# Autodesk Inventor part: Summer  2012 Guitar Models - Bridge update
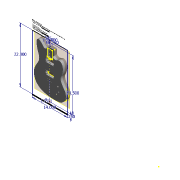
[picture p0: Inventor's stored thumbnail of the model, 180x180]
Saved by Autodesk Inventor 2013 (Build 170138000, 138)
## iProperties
Created: 2011-12
Part Number: Summer  2012 Guitar Models - Bridge update
Material: Generic
Document SubType Name: Modeling
Designer: Jeremy
Density: 1 g/cm^3
Author: Jeremy
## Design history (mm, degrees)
sketch "(ALL) Pocket Layout"
  geometry: L1 (-55.693, -76.531)-(-54.491, 0); L2 (-27.245, 0)-(-27.245, -267.97); L3 (-27.245, -267.97)-(-27.245, -279.73); L4 (-27.245, -279.73)-(-16.958, -279.73); L5 (-22.102, -267.97)-(-32.389, -267.97); L6 (-37.532, -279.73)-(-27.245, -279.73); L7 (-1.972, -79.756)-(-20.387, -79.756); L8 (-32.389, -267.97)-(-42.676, -267.97); L9 (-37.532, -279.73)-(-47.819, -279.73); L10 (-42.676, -267.97)-(-52.963, -267.97); L11 (-11.815, -267.97)-(-22.102, -267.97); L12 (8.442, -239.522)-(-62.932, -239.522); L13 (13.522, -237.236)-(-68.012, -237.236); L14 (-27.245, -239.522)-(-27.245, -237.236); L15 (-1.528, -267.97)-(-11.815, -267.97); L16 (8.442, -226.822)-(8.442, -239.522); L17 (-62.932, -239.522)-(-62.932, -226.822); L18 (-70.425, -226.822)-(-62.932, -226.822); L19 (-27.245, -129.921)-(-27.245, -127.635); L20 (-68.012, -90.297)-(13.522, -90.297); L21 (-68.012, -108.966)-(13.522, -108.966); L22 (8.442, -129.921)-(-62.932, -129.921); L23 (13.522, -127.635)-(-68.012, -127.635); L24 (-62.932, -100.711)-(-62.932, -88.011); L25 (-62.932, -129.921)-(-62.932, -117.221); L26 (-68.012, -127.635)-(-68.012, -90.297); L27 (-34.103, -79.756)-(-52.518, -79.756); L28 (8.442, -88.011)-(8.442, -100.711); L29 (8.442, -117.221)-(8.442, -129.921); L30 (13.522, -90.297)-(13.522, -127.635); L31 (-70.425, -100.711)-(-70.425, -117.221); L32 (-70.425, -117.221)-(-62.932, -117.221); L33 (-70.425, -108.966)-(-68.012, -108.966); L34 (-62.932, -100.711)-(-70.425, -100.711); L35 (-16.958, -279.73)-(-6.671, -279.73); L36 (-70.425, -210.312)-(-70.425, -226.822); L37 (-70.425, -218.567)-(-68.012, -218.567); L38 (-62.932, -210.312)-(-70.425, -210.312); L39 (-68.012, -237.236)-(-68.012, -199.898); L40 (-62.932, -210.312)-(-62.932, -197.612); L41 (15.935, -226.822)-(8.442, -226.822); L42 (15.935, -218.567)-(13.522, -218.567); L43 (-68.012, -218.567)-(13.522, -218.567); L44 (-68.012, -199.898)-(13.522, -199.898); L45 (-62.932, -197.612)-(8.442, -197.612); L46 (8.442, -210.312)-(15.935, -210.312); L47 (15.935, -210.312)-(15.935, -226.822); L48 (8.442, -197.612)-(8.442, -210.312); L49 (13.522, -199.898)-(13.522, -237.236); L50 (-54.491, 0)-(0, 0); L51 (-46.295, -13.03)-(-27.245, -13.03); L52 (-8.195, -13.03)-(-8.195, -63.83); L53 (-8.195, -63.83)-(-46.295, -63.83); L54 (-46.295, -63.83)-(-46.295, -13.03); L55 (-27.245, -13.03)-(-8.195, -13.03); L56 (0, 0)-(1.202, -76.531); L57 (15.935, -100.711)-(15.935, -117.221); L58 (15.935, -117.221)-(8.442, -117.221); L59 (15.935, -108.966)-(13.522, -108.966); L60 (8.442, -100.711)-(15.935, -100.711); L61 (-33.595, -80.264)-(-33.595, -87.503); L62 (-20.895, -80.264)-(-20.895, -87.503); L63 (-62.932, -88.011)-(-27.245, -88.011); L64 (-27.245, -88.011)-(8.442, -88.011); C1 r 1.587 at (-46.295, -13.03); C2 r 1.587 at (-46.295, -63.83); C3 r 1.587 at (-22.102, -267.97); C4 r 1.587 at (-27.245, -279.73); C5 r 1.587 at (-52.963, -267.97); C6 r 1.587 at (-42.676, -267.97); C7 r 1.587 at (-37.532, -279.73); C8 r 1.587 at (-32.389, -267.97); C9 r 1.587 at (-16.958, -279.73); C10 r 1.587 at (-11.815, -267.97); C11 r 1.587 at (-6.671, -279.73); C12 r 1.587 at (-1.528, -267.97); C13 r 1.587 at (-47.819, -279.73); C14 r 1.587 at (-8.195, -63.83); C15 r 1.587 at (-8.195, -13.03); C16 r 3.175 at (-52.963, -267.97); C17 r 3.175 at (-42.676, -267.97); C18 r 3.175 at (-32.389, -267.97); C19 r 3.175 at (-22.102, -267.97); C20 r 3.175 at (-11.815, -267.97); C21 r 3.175 at (-1.528, -267.97); C22 r 0.992 at (-68.012, -90.297); C23 r 0.992 at (13.522, -90.297); C24 r 0.992 at (13.522, -127.635); C25 r 0.992 at (-68.012, -127.635); C26 r 0.992 at (-68.012, -199.898); C27 r 0.992 at (13.522, -199.898); C28 r 0.992 at (13.522, -237.236); C29 r 0.992 at (-68.012, -237.236); A1 r 3.175 centre (-1.972, -76.581) between (-1.972, -79.756) and (1.202, -76.531); A2 r 3.175 centre (-52.518, -76.581) between (-55.693, -76.531) and (-52.518, -79.756); A3 r 0.508 centre (-34.103, -87.503) between (-34.103, -88.011) and (-33.595, -87.503); A4 r 0.508 centre (-20.387, -87.503) between (-20.895, -87.503) and (-20.387, -88.011); A5 r 0.508 centre (-20.387, -80.264) between (-20.387, -79.756) and (-20.895, -80.264); A6 r 0.508 centre (-34.103, -80.264) between (-33.595, -80.264) and (-34.103, -79.756); 25 further points
  constraints: 128 end point, 43 coincident, 35 centre point, 34 perpendicular, 29 equal radius, 27 parallel, 19 collinear, 17 equal length, 14 midpoint, 14 tangent, 12 point on circle, 9 point on line, 7 horizontal, 1 vertical, 1 other
  dimensions: "d0" = 3.175 diameter of C15; "d1" = 50.8 distance of L53.end L51.start; "d2" = 38.1 distance of L52.end L53.end; "d3" = 10.287 distance of L8.end L10.end; "d4" = 3.175 diameter of C9; "d5" = 71.374 distance of L22.start L22.end; "d7" = 16.51 distance of L31.start L31.end; "d8" = 7.493 distance of L31.end L25.end; "d9" = 37.338 distance of L20.end L23.start; "d10" = 81.534 distance of L23.start L23.end; "d11" = 188.214 distance between parallel lines of L15 L7; "d12" = 15.9258 distance between parallel lines of L53 L7; "d13" = 79.756 distance between parallel lines of L50 L27; "d14" = 35.687 distance between parallel lines of L2 L24 (= 0.5 x d5); "d18" = 28.448 distance between parallel lines of L8 L12; "d19" = 89.1 deg angle of L1 L27; "d20" = 89.1 deg angle of L7 L56 (= d19); "d21" = 56.896 dimension on A1 A2; "d22" = 3.175 radius of A2; "d24" = 11.7602 distance between parallel lines of L6 L8; "d25" = 10.287 distance of L6.start L3.end; "d190" = 8.255 distance between parallel lines of L63 L27; "d191" = 12.7 distance between parallel lines of L34 L63; "d192" = 12.7 distance between parallel lines of L62 L61; "d193" = 0.508 radius of A3; "d198" = 6.35 diameter of C16; "d224" = 1.98438 diameter of C22; "d229" = 54.49072 distance of L1.end L50.end (derived)
sketch "DC Profile"
  geometry: L1 (0.598, -38.095)-(0, 0); L2 (0.598, -38.095)-(6.428, -57.036); L3 (0, 0)-(-55.88, 0); L4 (-27.94, 0)-(-27.94, -264.048); L5 (8.442, -239.522)-(-62.932, -239.522) reference; L6 (8.442, -226.822)-(8.442, -239.522) reference; L7 (15.935, -226.822)-(8.442, -226.822) reference; L8 (15.935, -210.312)-(15.935, -226.822) reference; L9 (-27.94, -264.048)-(87.038, -330.431); L10 (87.038, -330.431)-(77.061, -347.71); C1 r 22.225 at (65.63, -275.47); C2 r 22.225 at (60.208, -319.588); C3 r 1.587 at (-1.528, -267.97) reference; C4 r 1.587 at (-6.671, -279.73) reference; C5 r 3.175 at (-1.528, -267.97) reference; C6 r 6.223 at (65.63, -275.47); C7 r 4.763 at (60.208, -319.588); C8 r 4.763 at (28.736, -339.371); A1 r 15.24 centre (76.454, -45.83) between (89.084, -54.359) and (66.661, -34.153); A2 r 577.126 centre (437.513, -476.355) between (66.661, -34.153) and (33.758, -63.977); A3 r 16.51 centre (22.207, -52.18) between (6.428, -57.036) and (33.758, -63.977); A4 r 116.188 centre (185.37, -119.388) between (89.084, -54.359) and (69.629, -129.58); A5 r 86.071 centre (155.369, -122.03) between (69.629, -129.58) and (82.565, -167.941); A6 r 609.6 centre (-433.07, -493.108) between (115.04, -226.297) and (82.565, -167.941); A7 r 121.92 centre (5.418, -279.659) between (115.845, -331.335) and (115.04, -226.297); A8 r 158.75 centre (-27.94, -264.048) between (-171.725, -331.335) and (115.845, -331.335); A9 r 121.92 centre (-61.298, -279.659) between (-170.92, -226.297) and (-171.725, -331.335); A10 r 12.7 centre (-55.88, -12.7) between (-55.88, 0) and (-67.52, -7.62); A11 r 609.6 centre (377.19, -493.108) between (-138.014, -167.259) and (-170.92, -226.297); A12 r 86.662 centre (-211.256, -120.935) between (-138.014, -167.259) and (-124.602, -119.803); A13 r 170.431 centre (-295.018, -122.03) between (-124.602, -119.803) and (-136.115, -60.412); A14 r 244.348 centre (124.259, 83.536) between (-117.009, 44.864) and (-102.671, -7.063); A15 r 279.4 centre (124.385, 40.602) between (-155.012, 41.929) and (-136.115, -60.412); A16 r 19.122 centre (-135.89, 41.838) between (-117.009, 44.864) and (-155.012, 41.929); A17 r 19.05 centre (-84.979, 0) between (-102.671, -7.063) and (-67.52, -7.62); A18 r 31.75 centre (28.736, -339.371) between (0.683, -324.504) and (47.295, -365.133); A19 r 38.1 centre (28.736, -339.371) between (-4.928, -321.53) and (51.006, -370.285); A20 r 1049.401 centre (927.915, -815.912) between (38.727, -258.609) and (0.683, -324.504); A21 r 1055.751 centre (927.915, -815.912) between (33.347, -255.236) and (-4.928, -321.53); A22 r 121.641 centre (-23.806, -266.435) between (47.295, -365.133) and (97.219, -278.661); A23 r 127.991 centre (-23.806, -266.435) between (51.006, -370.285) and (103.537, -279.299); A24 r 31.75 centre (65.63, -275.47) between (97.219, -278.661) and (38.727, -258.609); A25 r 38.1 centre (65.63, -275.47) between (103.537, -279.299) and (33.347, -255.236); 11 further points
  constraints: 51 point on circle, 30 centre point, 25 tangent, 12 end point, 7 coincident, 3 equal radius, 1 horizontal, 1 midpoint, 1 perpendicular, 1 point on line, 1 vertical, 10 other
  dimensions: "d78" = 121.92 radius of A9; "d79" = 121.92 radius of A7 (derived); "d80" = 609.6 radius of A6 (derived); "d81" = 116.18821 radius of A4; "d82" = 15.24 radius of A1; "d83" = 577.12575 radius of A2; "d84" = 609.6 radius of A11; "d85" = 86.66192 radius of A12; "d86" = 170.43088 radius of A13; "d87" = 279.4 radius of A15; "d88" = 19.12205 radius of A16; "d89" = 244.348 radius of A14; "d90" = 158.75 radius of A8; "d91" = 55.88 distance of L1.end L3.end; "d92" = 12.7 radius of A10; "d93" = 19.05 radius of A17; "d94" = 60.96 dimension on A16 L3; "d95" = 38.1 distance of L1.start L1.end; "d96" = 16.51 radius of A3; "d97" = 264.04829 distance of L4.start L4.end; "d98" = 107.95 distance from line of A16.centre L4; "d99" = 89.1 deg angle of L1 L3; "d181" = 121.6406 radius of A22; "d182" = 31.75 radius of A18; "d183" = 1049.401 radius of A20; "d184" = 73.787 distance of A24.centre A18.centre; "d185" = 6.35 radial gap between concentric circles of A21 A20; "d186" = 44.45 diameter of C1; "d307" = 60 deg angle of L9 L4; "d308" = 25.4 distance from line of A7.start L10; "d368" = 12.446 diameter of C6; "d370" = 9.525 diameter of C8
sketch "SC Profile"
  geometry: L1 (-26.687, -262.89)-(-26.687, 0); L2 (-220.362, -123.015)-(166.988, -123.015); L3 (-66.12, -280.484)-(12.746, -280.484); L4 (-26.687, -262.89)-(-26.687, -280.484); L5 (-55.88, 0)-(-55.88, -177.8); L6 (-26.687, -79.756)-(1.253, -79.756); L7 (0.598, -38.095)-(1.253, -79.756); L8 (0.598, -38.095)-(7.487, -57.656); L9 (0, 0)-(-55.88, 0); L10 (0.598, -38.095)-(0, 0); L11 (-179.087, -379.544)-(125.713, -379.544); L12 (83.941, -344.355)-(84.908, -343.013); L13 (-26.687, -280.484)-(83.941, -344.355); C1 r 22.225 at (68.182, -287.517); C2 r 22.225 at (58.341, -330.864); C3 r 6.223 at (68.182, -287.517); C4 r 4.762 at (58.341, -330.864); C5 r 4.763 at (25.036, -347.375); A1 r 152.4 centre (221.61, -107.092) between (86.197, -37.17) and (75.3, -149.743); A2 r 95.504 centre (166.988, -123.015) between (75.3, -149.743) and (90.264, -179.887); A3 r 335.28 centre (-179.087, -379.544) between (118.818, -225.71) and (90.264, -179.887); A4 r 119.38 centre (-66.12, -280.484) between (-172.193, -225.71) and (-175.141, -329.126); A5 r 177.8 centre (-55.88, -177.8) between (-55.88, 0) and (-105.911, -7.184); A6 r 55.88 centre (-90.187, -60.806) between (-105.911, -7.184) and (-136.332, -92.321); A7 r 95.504 centre (-220.362, -123.015) between (-143.638, -179.887) and (-126.087, -138.29); A8 r 63.5 centre (-188.77, -128.134) between (-126.087, -138.29) and (-136.332, -92.321); A9 r 335.28 centre (125.713, -379.544) between (-143.638, -179.887) and (-172.193, -225.71); A10 r 16.51 centre (23.059, -52.172) between (7.487, -57.656) and (36.704, -61.467); A11 r 575.056 centre (511.96, -385.228) between (65.043, -23.352) and (36.704, -61.467); A12 r 12.7 centre (74.913, -31.344) between (86.197, -37.17) and (65.043, -23.352); A13 r 119.38 centre (12.746, -280.484) between (121.767, -329.126) and (118.818, -225.71); A14 r 162.56 centre (-26.687, -262.89) between (-175.141, -329.126) and (121.767, -329.126); A15 r 31.75 centre (68.182, -287.517) between (99.288, -293.875) and (43.115, -268.03); A16 r 38.1 centre (68.182, -287.517) between (105.51, -295.147) and (38.102, -264.132); A17 r 1049.401 centre (871.609, -912.112) between (43.115, -268.03) and (-1.377, -329.755); A18 r 1055.751 centre (871.609, -912.112) between (38.102, -264.132) and (-6.659, -326.231); A19 r 31.75 centre (25.036, -347.375) between (-1.377, -329.755) and (40.903, -374.875); A20 r 38.1 centre (25.036, -347.375) between (-6.659, -326.231) and (44.077, -380.375); A21 r 121.641 centre (-19.888, -269.514) between (40.903, -374.875) and (99.288, -293.875); A22 r 127.991 centre (-19.888, -269.514) between (44.077, -380.375) and (105.51, -295.147); 9 further points
  constraints: 45 point on circle, 27 centre point, 26 end point, 21 tangent, 7 coincident, 4 perpendicular, 3 equal radius, 2 parallel, 2 point on line, 1 collinear, 1 horizontal, 1 midpoint, 1 vertical, 4 other
  dimensions: "d100" = 575.056 radius of A11; "d101" = 16.51 radius of A10; "d102" = 162.56 radius of A14; "d103" = 119.38 radius of A4; "d104" = 119.38 radius of A13 (derived); "d105" = 335.28 radius of A9; "d106" = 335.28 radius of A3 (derived); "d107" = 95.504 radius of A7; "d108" = 63.5 radius of A8; "d109" = 95.504 radius of A2 (derived); "d110" = 152.4 radius of A1; "d111" = 12.7 radius of A12; "d112" = 99.06 distance between parallel lines of L11 L3; "d113" = 304.8 distance of L11.start L11.end; "d114" = 425.45 dimension on A14 L9; "d115" = 157.46865 distance between parallel lines of L2 L3; "d116" = 161.5 deg angle of L8 L10; "d117" = 38.1 distance of L7.start L9.start; "d118" = 52.1716 distance from line of A10.centre L9; "d119" = 55.88 distance of L9.start L5.start; "d120" = 177.8 radius of A5; "d121" = 55.88 radius of A6; "d122" = 63.5 distance from line of L1 A6.centre; "d123" = 79.756 distance between parallel lines of L6 L9; "d124" = 27.94 distance of L6.start L6.end; "d125" = 89.1 deg angle of L6 L7; "d126" = 101.6 distance from line of A12.centre L1; "d127" = 31.3436 distance from line of A12.centre L9; "d316" = 121.6406 radius of A21; "d317" = 31.75 radius of A19; "d318" = 1049.401 radius of A17; "d319" = 73.787 distance of A15.centre A19.centre; "d320" = 6.35 radial gap between concentric circles of A18 A17; "d321" = 44.45 diameter of C1; "d324" = 25.4 dimension on A20 A14; "d325" = 25.4 dimension on A16 A13; "d326" = 60 deg angle of L13 L1; "d373" = 12.446 diameter of C3; "d374" = 9.525 diameter of C4
sketch "Surf Profile"
  geometry: L1 (-54.483, 0)-(0, 0); L2 (0.798, -50.794)-(0, 0); L3 (-179.087, -379.544)-(125.713, -379.544); L4 (91.985, -330.787)-(89.52, -344.766); L5 (91.985, -330.787)-(38.635, -321.381); L6 (-27.241, 0)-(-27.241, -287.724); C1 r 22.225 at (63.065, -329.775); C2 r 22.225 at (53.07, -286.463); C3 r 6.223 at (53.07, -286.463); C4 r 4.762 at (63.065, -329.775); C5 r 4.762 at (40.257, -359.129); A1 r 32.915 centre (28.914, -33.681) between (0.798, -50.794) and (48.288, -60.289); A2 r 31.75 centre (66.977, -85.956) between (93.448, -68.424) and (48.288, -60.289); A3 r 63.5 centre (145.535, -204.345) between (89.412, -174.638) and (88.407, -232.07); A4 r 133.35 centre (-28.446, -112.254) between (89.412, -174.638) and (104.165, -98.227); A5 r 66.675 centre (37.86, -105.241) between (104.165, -98.227) and (93.448, -68.424); A6 r 292.1 centre (351.196, -104.538) between (88.407, -232.07) and (118.036, -280.49); A7 r 128.27 centre (-59.431, -278.208) between (-175.37, -223.332) and (-103.706, -398.595); A8 r 294.107 centre (-2.19, -122.563) between (-103.706, -398.595) and (-83.78, -405.126); A9 r 368.3 centre (18.392, -51.282) between (-83.78, -405.126) and (59.079, -417.328); A10 r 85.725 centre (49.609, -332.128) between (59.079, -417.328) and (118.036, -280.49); A11 r 21.082 centre (-75.17, 4.064) between (-92.594, -7.804) and (-54.483, 0); A12 r 444.5 centre (226.397, -413.498) between (-148.498, -174.681) and (-175.37, -223.332); A13 r 88.9 centre (-223.477, -126.918) between (-148.498, -174.681) and (-141.247, -93.133); A14 r 152.4 centre (-218.554, -93.593) between (-92.594, -7.804) and (-126.344, 27.746); A15 r 254 centre (93.695, 3.396) between (-160.171, 11.645) and (-141.247, -93.133); A16 r 21.082 centre (-139.1, 10.961) between (-126.344, 27.746) and (-160.171, 11.645); A17 r 31.75 centre (40.257, -359.129) between (8.81, -354.753) and (66.507, -376.99); A18 r 38.1 centre (40.257, -359.129) between (2.521, -353.878) and (71.757, -380.562); A19 r 121.641 centre (-34.061, -308.562) between (66.507, -376.99) and (83.846, -278.658); A20 r 127.991 centre (-34.061, -308.562) between (71.757, -380.562) and (90.001, -277.097); A21 r 31.75 centre (53.07, -286.463) between (83.846, -278.658) and (22.023, -279.82); A22 r 38.1 centre (53.07, -286.463) between (90.001, -277.097) and (15.814, -278.491); A23 r 1055.751 centre (1048.196, -499.393) between (15.814, -278.491) and (2.521, -353.878); A24 r 1049.401 centre (1048.196, -499.393) between (22.023, -279.82) and (8.81, -354.753); 8 further points
  constraints: 49 point on circle, 29 centre point, 22 tangent, 12 end point, 7 coincident, 3 perpendicular, 2 equal radius, 1 horizontal, 1 midpoint, 12 other
  dimensions: "d128" = 54.483 distance of L1.start L1.end; "d129" = 50.8 distance of L2.start L1.end; "d130" = 21.082 radius of A11; "d131" = 4.064 distance from line of A11.centre L1; "d132" = 152.4 radius of A14; "d133" = 21.082 radius of A16; "d134" = 254 radius of A15; "d135" = 88.9 radius of A13; "d136" = 444.5 radius of A12; "d137" = 368.3 radius of A9; "d138" = 85.725 radius of A10; "d139" = 292.1 radius of A6; "d140" = 63.5 radius of A3; "d141" = 133.35 radius of A4; "d142" = 66.675 radius of A5; "d143" = 31.75 radius of A2; "d144" = 128.27 radius of A7; "d145" = 89.1 deg angle of L2 L1; "d333" = 304.8 distance of L3.start L3.end; "d334" = 121.6406 radius of A19; "d335" = 31.75 radius of A17; "d336" = 1049.401 radius of A24; "d337" = 73.787 distance of A21.centre A17.centre; "d338" = 6.35 radial gap between concentric circles of A23 A24; "d339" = 44.45 diameter of C2; "d345" = 100 deg angle of L5 L6; "d346" = 19.05 dimension on A18 A10; "d347" = 19.05 dimension on A22 A6 (derived); "d375" = 12.446 diameter of C3; "d376" = 9.525 diameter of C4; "d377" = 9.525 diameter of C5
sketch "Wave Profile"
  geometry: L1 (-54.491, 0)-(0, 0); L2 (-54.491, 0)-(0, 0) reference; L3 (0.854, -54.356)-(0, 0) reference; L4 (101.607, -312.825)-(80.422, -371.029); L5 (-27.245, -279.73)-(97.17, -325.014); L6 (-27.245, -267.97)-(-27.245, -279.73) reference; C1 r 22.225 at (70.981, -262.416); C2 r 22.225 at (73.302, -306.806); C3 r 1.587 at (-27.245, -279.73) reference; C4 r 6.223 at (70.981, -262.416); C5 r 4.763 at (73.302, -306.806); C6 r 4.762 at (45.744, -331.753); A1 r 1016 centre (1059.802, 155.233) between (97.426, -170.478) and (121.144, -233.582); A2 r 99.604 centre (-132.305, -92.495) between (-72.998, -12.472) and (-115.009, 5.596); A3 r 1016 centre (-1114.294, 155.233) between (-175.636, -233.582) and (-151.918, -170.478); A4 r 144.273 centre (-29.023, -43.312) between (-173.296, -43.314) and (-156.675, -110.542); A5 r 40.64 centre (33.94, -35.941) between (33.94, -76.581) and (74.463, -39.022); A6 r 144.356 centre (-25.542, -43.273) between (102.183, -110.542) and (118.802, -41.422); A7 r 38.1 centre (112.453, -41.911) between (79.968, -22.002) and (74.463, -39.022); A8 r 19.482 centre (96.579, -32.182) between (113.19, -22.002) and (79.968, -22.002); A9 r 38.1 centre (80.706, -41.911) between (118.802, -41.422) and (113.19, -22.002); A10 r 35.739 centre (33.94, -40.842) between (0.854, -54.356) and (33.94, -76.581) reference; A11 r 395.287 centre (-27.246, -1.588) between (-124.547, -384.712) and (70.056, -384.712); A12 r 177.8 centre (-11.371, -301.625) between (-175.636, -233.582) and (-189.171, -301.625); A13 r 85.725 centre (-103.446, -301.625) between (-189.171, -301.625) and (-124.547, -384.712); A14 r 85.725 centre (48.954, -301.625) between (70.056, -384.712) and (134.679, -301.625) reference; A15 r 177.8 centre (-43.121, -301.625) between (134.679, -301.625) and (121.144, -233.582); A16 r 76.2 centre (169.604, -146.05) between (102.183, -110.542) and (97.426, -170.478); A17 r 76.2 centre (-224.096, -146.05) between (-151.918, -170.478) and (-156.675, -110.542) reference; A18 r 49.664 centre (-123.633, -43.313) between (-115.009, 5.596) and (-173.296, -43.314) reference; A19 r 6.35 centre (-54.491, -6.35) between (-54.491, 0) and (-60.841, -6.35); A20 r 7.62 centre (-68.461, -6.35) between (-72.998, -12.472) and (-60.841, -6.35); A21 r 1055.751 centre (1014.013, -644.913) between (35.674, -248.096) and (9.493, -320.029); A22 r 1049.401 centre (1014.013, -644.913) between (41.559, -250.483) and (15.535, -321.983); A23 r 31.75 centre (70.981, -262.416) between (102.644, -260.073) and (41.559, -250.483); A24 r 38.1 centre (70.981, -262.416) between (108.977, -259.605) and (35.674, -248.096); A25 r 121.641 centre (-18.665, -269.049) between (68.494, -353.901) and (102.644, -260.073); A26 r 127.991 centre (-18.665, -269.049) between (73.043, -358.33) and (108.977, -259.605); A27 r 31.75 centre (45.744, -331.753) between (15.535, -321.983) and (68.494, -353.901); A28 r 38.1 centre (45.744, -331.753) between (9.493, -320.029) and (73.043, -358.33); 19 further points
  constraints: 58 point on circle, 33 centre point, 25 tangent, 8 end point, 7 coincident, 5 horizontal alignment, 4 equal radius, 1 horizontal, 1 perpendicular, 1 point on line, 27 other
  dimensions: "d281" = 38.1 radius of A9; "d284" = 177.8 radius of A12; "d285" = 1016 radius of A3; "d290" = 7.62 radius of A20; "d291" = 6.35 radius of A19; "d293" = 40.64 radius of A5; "d301" = 144.2732 radius of A4; "d353" = 121.6406 radius of A25; "d354" = 31.75 radius of A27; "d355" = 1049.401 radius of A22; "d356" = 73.787 distance of A23.centre A27.centre; "d357" = 6.35 radial gap between concentric circles of A21 A22; "d358" = 44.45 diameter of C1; "d360" = 19.05 dimension on A24 A15; "d361" = 19.05 dimension on A28 A11; "d363" = 110 deg angle of L5 L6; "d378" = 12.446 diameter of C4; "d379" = 9.525 diameter of C5; "d380" = 9.525 diameter of C6
sketch "Flame Profile"
  geometry: L1 (0, 0)-(-54.483, 0); L2 (0, 0)-(4.589, -65.626); L3 (-54.483, 0)-(-59.072, -65.626); L4 (-27.241, 0)-(-27.241, -264.048); L5 (87.474, -330.28)-(73.626, -355.66); L6 (87.474, -330.28)-(-27.241, -264.048); C1 r 6.223 at (64.748, -275.851); C2 r 22.225 at (64.748, -275.851); C3 r 4.763 at (60.391, -320.087); C4 r 22.225 at (60.391, -320.087); C5 r 4.763 at (29.406, -340.623); A1 r 15.875 centre (20.064, -62.087) between (4.589, -65.626) and (24.621, -77.294); A2 r 609.6 centre (389.165, -466.828) between (-141.475, -166.773) and (-173.412, -232.053); A3 r 609.6 centre (-443.648, -466.828) between (118.929, -232.053) and (86.992, -166.773); A4 r 158.75 centre (-27.241, -264.048) between (-172.306, -328.529) and (117.823, -328.529); A5 r 121.92 centre (-60.896, -279.008) between (-173.412, -232.053) and (-172.306, -328.529); A6 r 73.025 centre (-205.041, -130.829) between (-141.475, -166.773) and (-142.092, -93.815); A7 r 15.875 centre (-74.547, -62.087) between (-79.104, -77.294) and (-59.072, -65.626); A8 r 4.763 centre (-128.841, -22.86) between (-124.1, -22.414) and (-132.17, -19.454); A9 r 63.5 centre (-60.879, -16.466) between (-124.1, -22.414) and (-79.104, -77.294); A10 r 60.853 centre (-89.635, -62.972) between (-132.17, -19.454) and (-142.092, -93.815); A11 r 121.92 centre (6.414, -279.008) between (117.823, -328.529) and (118.929, -232.053); A12 r 73.025 centre (150.559, -130.829) between (87.609, -93.815) and (86.992, -166.773); A13 r 60.853 centre (35.152, -62.972) between (87.609, -93.815) and (77.687, -19.454); A14 r 4.763 centre (74.359, -22.86) between (77.687, -19.454) and (69.617, -22.414); A15 r 63.5 centre (6.396, -16.466) between (24.621, -77.294) and (69.617, -22.414); A16 r 31.75 centre (64.748, -275.851) between (96.405, -278.28) and (37.447, -259.643); A17 r 38.1 centre (64.748, -275.851) between (102.736, -278.765) and (31.987, -256.401); A18 r 1049.401 centre (939.81, -795.352) between (37.447, -259.643) and (1.002, -326.436); A19 r 1055.751 centre (939.81, -795.352) between (31.987, -256.401) and (-4.679, -323.598); A20 r 121.641 centre (-24.879, -268.974) between (48.579, -365.93) and (96.405, -278.28); A21 r 127.991 centre (-24.879, -268.974) between (52.414, -370.991) and (102.736, -278.765); A22 r 31.75 centre (29.406, -340.623) between (1.002, -326.436) and (48.579, -365.93); A23 r 38.1 centre (29.406, -340.623) between (-4.679, -323.598) and (52.414, -370.991); 12 further points
  constraints: 47 point on circle, 28 centre point, 19 tangent, 13 end point, 8 symmetric about line, 7 coincident, 5 equal radius, 1 horizontal, 1 midpoint, 1 vertical, 8 other
  dimensions: "d249" = 121.92 radius of A5; "d250" = 121.92 radius of A11 (derived); "d251" = 609.6 radius of A3 (derived); "d252" = 158.75 radius of A4; "d253" = 264.04829 distance of L4.start L4.end; "d254" = 63.5 radius of A9; "d255" = 4 deg angle of L4 L3; "d256" = 15.875 radius of A1; "d257" = 31.83055 distance from line of L4 L3.end; "d258" = 47.30596 distance from line of L4 A7.centre; "d259" = 54.483 distance of L1.start L1.end; "d260" = 4.7625 radius of A8; "d261" = 60.85266 radius of A10; "d262" = 101.6 distance from line of L4 A8.centre; "d263" = 62.39352 distance from line of L4 A10.centre; "d264" = 22.86 distance from line of A8.centre L1; "d265" = 177.8 distance from line of L4 A6.centre; "d267" = 104.775 distance edge to line of A6 L4; "d268" = 155.575 dimension on A5 L4; "d388" = 121.6406 radius of A20; "d389" = 31.75 radius of A22; "d390" = 1049.401 radius of A18; "d391" = 73.787 distance of A16.centre A22.centre; "d392" = 6.35 radial gap between concentric circles of A19 A18; "d393" = 44.45 diameter of C2; "d395" = 12.446 diameter of C1; "d396" = 9.525 diameter of C5; "d397" = 60 deg angle of L6 L4; "d398" = 25.4 dimension on A17 A11; "d399" = 25.4 dimension on A23 A4
sketch "Axe Profile"
  geometry: L1 (-54.491, 0)-(0, 0) reference; L2 (-55.693, -76.531)-(-54.491, 0) reference; L3 (0, 0)-(1.202, -76.531) reference; L4 (-54.491, 0)-(0, 0) reference; L5 (97.445, -286.779)-(38.688, -361.595); L6 (-27.245, 0)-(-27.245, -513.999); L7 (11.122, -53.39)-(0, 0); L8 (-103.866, 51.709)-(-78.35, 51.709); L9 (38.465, -287.37)-(84.039, -229.34); L10 (144.205, -221.904)-(10.855, -391.7); L11 (103.148, -313.17)-(123.495, -287.263); C1 r 6.223 at (84.039, -229.34); C2 r 22.225 at (84.039, -229.34); C3 r 4.763 at (38.465, -287.37); C4 r 4.763 at (72.422, -272.245); C5 r 22.225 at (72.422, -272.245); C6 r 3.175 at (-1.528, -267.97) reference; A1 r 31.75 centre (84.039, -229.34) between (114.858, -236.974) and (59.797, -208.838); A2 r 38.1 centre (84.039, -229.34) between (121.021, -238.501) and (54.948, -204.737); A3 r 1055.751 centre (861.063, -886.491) between (54.948, -204.737) and (7.668, -264.94); A4 r 1049.401 centre (861.063, -886.491) between (59.797, -208.838) and (12.8, -268.678); A5 r 31.75 centre (38.465, -287.37) between (12.8, -268.678) and (53.186, -315.501); A6 r 38.1 centre (38.465, -287.37) between (7.668, -264.94) and (56.131, -321.127); A7 r 121.641 centre (-3.214, -207.726) between (53.186, -315.501) and (114.858, -236.974); A8 r 127.991 centre (-3.214, -207.726) between (56.131, -321.127) and (121.021, -238.501); A9 r 254.042 centre (344.272, -65.346) between (118.805, 51.709) and (144.205, -221.904); A10 r 254 centre (-103.291, -164.793) between (10.855, -391.7) and (144.205, -221.904); A11 r 127 centre (10.855, -413.46) between (-81.509, -326.294) and (-109.795, -453.116); A12 r 57.15 centre (-39.945, -365.518) between (10.855, -391.7) and (-81.509, -326.294); A13 r 228.6 centre (58.48, -324.879) between (-140.694, -212.683) and (-153.56, -410.301); A14 r 76.2 centre (-82.88, -381.827) between (-153.56, -410.301) and (-109.795, -453.116); A15 r 101.6 centre (-229.215, -162.819) between (-140.694, -212.683) and (-129.255, -144.638); A16 r 25.4 centre (-154.245, -149.183) between (-129.255, -144.638) and (-177.422, -138.791); A17 r 158.75 centre (-27.245, -87.326) between (-103.866, 51.709) and (-177.422, -138.791); A18 r 88.9 centre (130.764, -36.383) between (118.805, 51.709) and (42.605, -24.928); A19 r 152.4 centre (-108.525, -5.291) between (35.562, -54.937) and (42.605, -24.928); A20 r 12.7 centre (23.555, -50.8) between (11.122, -53.39) and (35.562, -54.937); A21 r 69.85 centre (-47.441, 10.536) between (-103.866, 51.709) and (-117.032, 4.529); A22 r 31.75 centre (-85.4, 7.259) between (-117.032, 4.529) and (-54.491, 0); 5 further points
  constraints: 45 point on circle, 27 centre point, 16 end point, 16 tangent, 7 coincident, 3 equal radius, 3 parallel, 2 perpendicular, 1 collinear, 1 horizontal, 1 horizontal alignment, 1 midpoint, 1 point on line, 1 vertical alignment, 4 other
  dimensions: "d401" = 121.6406 radius of A7; "d402" = 31.75 radius of A5; "d403" = 1049.401 radius of A4; "d404" = 73.787 distance of A1.centre A5.centre; "d405" = 6.35 radial gap between concentric circles of A3 A4; "d406" = 44.45 diameter of C2; "d408" = 12.446 diameter of C1; "d409" = 9.525 diameter of C3; "d412" = 57.15 radius of A12; "d413" = 127 radius of A11; "d414" = 50.8 horizontal distance of A11.centre A12.centre; "d415" = 254 radius of A10; "d417" = 228.6 radius of A13; "d418" = 25.4 radius of A16; "d419" = 101.6 radius of A15; "d420" = 504.825 vertical distance of A11.end L8.start; "d421" = 69.85 horizontal distance of A11.end A12.centre; "d422" = 12.7 distance from line of L6 A12.centre; "d423" = 142.875 distance edge to line of A13 L6; "d424" = 127 distance from line of L6 A16.centre; "d425" = 63.5 vertical distance of A13.start A16.centre; "d426" = 76.2 radius of A14; "d427" = 158.75 radius of A17; "d428" = 190.5 vertical distance of A16.end L8.start; "d429" = 171.45 distance from line of L10.start L6; "d430" = 215.9 distance of L10.start L10.end; "d432" = 117.475 distance edge to line of A9 L6; "d434" = 50.8 distance from line of A20.centre L1; "d435" = 50.8 distance from line of A20.centre L6; "d436" = 12.7 radius of A20; "d437" = 152.4 radius of A19; "d438" = 88.9 radius of A18; "d439" = 69.85 distance from line of A18.end L6; "d441" = 76.2 dimension on A22 L8; "d442" = 69.85 radius of A21; "d443" = 31.75 radius of A22; "d444" = 146.05 distance from line of A9.start L6; "d447" = 15.45354 dimension on A2 A9 (derived); "d448" = 15.45354 dimension on A6 A12 (derived); "d455" = 3.175 dimension on C6 A6; "d456" = 20.78559 distance between parallel lines of L11 L5 (derived)
sketch "Tear drop Profile"
  geometry: L1 (-146.986, -472.783)-(-59.895, -399.705); L2 (5.412, -399.705)-(92.503, -472.783); L3 (-165.354, -450.893)-(110.871, -450.893); L4 (-165.354, -479.468)-(110.871, -479.468); L5 (138.269, -442.777)-(34.224, -91.525); L6 (-88.707, -91.525)-(-192.752, -442.777); L7 (-63.616, -6.82)-(-88.707, -91.525); L8 (34.224, -91.525)-(9.133, -6.82); L9 (-64.417, -9.525)-(9.934, -9.525); L10 (-54.483, 0)-(-54.682, -12.698); L11 (0, 0)-(0.199, -12.698); L12 (0, 0)-(1.202, -76.531) reference; L13 (-153.513, -377.383)-(-174.487, -448.188); L14 (-102.662, -410.723)-(-159.231, -458.19); L15 (48.179, -410.723)-(104.748, -458.19); L16 (99.03, -377.383)-(120.004, -448.188); L17 (0, 0)-(-54.483, 0); L18 (-54.491, 0)-(0, 0) reference; L19 (17.84, -205.232)-(5.08, -205.232); L20 (5.08, -211.582)-(17.84, -211.582); L21 (5.08, -205.232)-(5.08, -211.582); L22 (59.237, -243.044)-(75.398, -297.602); L23 (58.655, -302.562)-(37.719, -263.855); L24 (11.176, -253.518)-(11.176, -320.416); L25 (5.08, -121.323)-(8.446, -121.323); L26 (5.08, -115.951)-(17.84, -115.951); L27 (67.582, -317.57)-(37.566, -335.424); L28 (70.828, -323.027)-(40.812, -340.882); L29 (21.015, -125.476)-(21.015, -202.057); L30 (5.08, -122.301)-(17.84, -122.301); L31 (5.08, -115.951)-(5.08, -122.301); L32 (27.365, -125.476)-(27.365, -234.988); L33 (27.25, -112.7)-(81.487, -295.799); L34 (4.826, -320.416)-(4.826, -115.951); L35 (138.269, -442.777)-(34.224, -91.525); L36 (21.015, -214.757)-(21.015, -230.541); L37 (43.453, -234.474)-(20.269, -241.341); L38 (8.442, -129.921)-(-62.932, -129.921) reference; L39 (8.442, -117.221)-(8.442, -129.921) reference; L40 (15.935, -100.711)-(15.935, -117.221) reference; L41 (15.935, -117.221)-(8.442, -117.221) reference; L42 (8.442, -100.711)-(15.935, -100.711) reference; L43 (8.442, -88.011)-(8.442, -100.711) reference; L44 (-62.932, -197.612)-(8.442, -197.612) reference; L45 (8.442, -197.612)-(8.442, -210.312) reference; L46 (8.442, -210.312)-(15.935, -210.312) reference; L47 (15.935, -210.312)-(15.935, -226.822) reference; L48 (15.935, -226.822)-(8.442, -226.822) reference; L49 (8.442, -226.822)-(8.442, -239.522) reference; L50 (8.442, -239.522)-(-62.932, -239.522) reference; C1 r 26.543 at (37.719, -263.855); C2 r 17.462 at (58.655, -302.562); C3 r 17.462 at (28.638, -320.416); C4 r 0.992 at (13.522, -127.635) reference; C5 r 0.992 at (13.522, -199.898) reference; C6 r 0.992 at (13.522, -237.236) reference; C7 r 3.175 at (-1.528, -267.97) reference; C8 r 6.223 at (37.719, -263.855); C9 r 4.763 at (58.655, -302.562); C10 r 4.762 at (28.638, -320.416); A1 r 28.575 centre (-165.354, -450.893) between (-192.752, -442.777) and (-146.986, -472.783); A2 r 28.575 centre (110.871, -450.893) between (92.503, -472.783) and (138.269, -442.777); A3 r 50.8 centre (-27.241, -438.62) between (5.412, -399.705) and (-59.895, -399.705); A4 r 9.525 centre (-54.483, -9.525) between (-54.483, 0) and (-63.616, -6.82); A5 r 101.6 centre (-156.27, -11.103) between (-82.736, -81.212) and (-54.682, -12.698); A6 r 101.6 centre (101.787, -11.103) between (0.199, -12.698) and (28.253, -81.212); A7 r 9.525 centre (0, -9.525) between (9.133, -6.82) and (0, 0); A8 r 9.525 centre (-165.354, -450.893) between (-174.487, -448.188) and (-155.829, -450.893); A9 r 31.75 centre (-123.071, -386.401) between (-102.662, -410.723) and (-153.513, -377.383); A10 r 9.525 centre (110.871, -450.893) between (101.346, -450.893) and (120.004, -448.188); A11 r 31.75 centre (68.588, -386.401) between (99.03, -377.383) and (48.179, -410.723); A12 r 31.75 centre (-123.071, -386.401) between (-153.513, -377.383) and (-102.662, -410.723); A13 r 9.525 centre (-165.354, -450.893) between (-155.829, -450.893) and (-174.487, -448.188); A14 r 9.525 centre (110.871, -450.893) between (120.004, -448.188) and (101.346, -450.893); A15 r 31.75 centre (68.588, -386.401) between (48.179, -410.723) and (99.03, -377.383); A16 r 25.4 centre (9.87, -98.739) between (34.224, -91.525) and (28.253, -81.212); A17 r 25.4 centre (-64.353, -98.739) between (-82.736, -81.212) and (-88.707, -91.525); A18 r 9.525 centre (17.84, -125.476) between (27.365, -125.476) and (17.84, -115.951); A19 r 11.448 centre (16.274, -115.951) between (27.25, -112.7) and (4.826, -115.951); A20 r 17.462 centre (58.655, -302.562) between (67.582, -317.57) and (75.398, -297.602); A21 r 23.812 centre (58.655, -302.562) between (70.828, -323.027) and (81.487, -295.799); A22 r 17.462 centre (28.638, -320.416) between (11.176, -320.416) and (37.566, -335.424); A23 r 23.813 centre (28.638, -320.416) between (4.826, -320.416) and (40.812, -340.882); A24 r 3.175 centre (17.84, -125.476) between (21.015, -125.476) and (17.84, -122.301); A25 r 3.175 centre (17.84, -202.057) between (17.84, -205.232) and (21.015, -202.057); A26 r 3.175 centre (17.84, -214.757) between (21.015, -214.757) and (17.84, -211.582); A27 r 3.175 centre (30.54, -234.988) between (27.365, -234.988) and (31.441, -238.032); A28 r 19.05 centre (1.965, -230.541) between (15.111, -244.327) and (21.015, -230.541); A29 r 12.7 centre (47.06, -246.651) between (59.237, -243.044) and (43.453, -234.474); A30 r 12.7 centre (23.876, -253.518) between (20.269, -241.341) and (11.176, -253.518); 7 further points
  constraints: 70 end point, 65 point on circle, 61 tangent, 36 centre point, 14 coincident, 12 parallel, 11 point on line, 10 equal radius, 4 equal length, 3 collinear, 3 horizontal, 2 horizontal alignment, 1 perpendicular
  dimensions: "d230" = 54.483 distance of L11.start L10.start; "d231" = 9.525 radius of A4; "d232" = 333.375 dimension on A2 A1; "d233" = 100 deg angle of L2 L1; "d234" = 33 deg angle of L5 L7; "d235" = 57.15 diameter of A1; "d236" = 3.175 distance from line of point (-27.242, -476.293) L4; "d237" = 50.8 radius of A3; "d238" = 12.7 distance of L10.start L10.end; "d240" = 101.6 radius of A5; "d241" = 1.8 deg angle of L11 L10; "d243" = 19.05 radial gap between concentric circles of A1 A8; "d244" = 31.75 radius of A11; "d269" = 25.4 radius of A16; "d481" = 3.61564 distance between parallel lines of L34 L39; "d482" = 0.254 distance between parallel lines of L34 L31; "d483" = 53.086 diameter of C1; "d484" = 34.925 diameter of C2; "d485" = 12.7 radius of A29; "d486" = 19.05 distance between parallel lines of L5 L22; "d487" = 6.35 distance between parallel lines of L22 L33; "d488" = 6.35 distance between parallel lines of L28 L27; "d489" = 6.35 distance between parallel lines of L32 L36; "d490" = 3.175 radius of A24; "d491" = 1.27 distance between parallel lines of L20 L46; "d492" = 1.27 distance between parallel lines of L41 L26; "d493" = 5.08 distance between parallel lines of L36 L47; "d494" = 19.05 radius of A28; "d502" = 12.446 diameter of C8; "d503" = 9.525 diameter of C9; "d504" = 9.525 diameter of C10
sketch "14\"x22\" Body Blank"
  geometry: L1 (-205.045, 80.01)-(150.555, 80.01); L2 (150.555, 80.01)-(150.555, -478.79); L3 (150.555, -478.79)-(-205.045, -478.79); L4 (-205.045, -478.79)-(-205.045, 80.01); L5 (-27.245, 80.01)-(-27.245, -478.79); L6 (-27.245, 0)-(-27.245, -267.97) reference; L7 (-27.94, 0)-(-27.94, -264.048) reference; L8 (-205.045, -478.79)-(150.555, -478.79); L9 (150.555, -478.79)-(150.555, -485.14); L10 (150.555, -485.14)-(-205.045, -485.14); L11 (-205.045, -485.14)-(-205.045, -478.79); C1 r 4.763 at (-27.245, 60.96); C2 r 12.7 at (-27.245, 60.96); C3 r 4.763 at (-27.245, -459.74); C4 r 12.7 at (-27.245, -459.74); 1 further point
  constraints: 18 end point, 5 parallel, 4 centre point, 2 coincident, 2 equal radius, 2 horizontal, 2 midpoint, 2 perpendicular, 2 point on line, 1 collinear
  dimensions: "d202" = 355.6 distance of L2.end L3.end; "d203" = 558.8 distance of L3.end L1.start; "d219" = 9.525 diameter of C1; "d220" = 25.4 diameter of C2; "d221" = 520.7 distance of C3.centre C1.centre; "d518" = 19.05 distance from line of L1 C1.centre (derived); "d519" = 19.05 distance from line of C3.centre L3 (derived); "d520" = 14.2875 distance edge to line of C1 L1 (derived); "d526" = 6.35 distance of L8.end L9.end
extrude "Body Blank" new body sketch "14\"x22\" Body Blank" distance "d204" = 44.45; taper "d205" = 0 deg
extrude "(All) Neck Pocket" cut sketch "(ALL) Pocket Layout" distance "d194" = 16.637; taper "d195" = 0 deg
extrude "(All) Pickups/ Bridge holes" cut sketch "(ALL) Pocket Layout" distance "d196" = 25.4; taper "d197" = 0 deg
fillet "(All) Pocket fillets" dims "d206" = 0.508
extrude "(All) Neck holes" cut sketch "(ALL) Pocket Layout" stored distance "d222" = 25.4; taper "d223" = 0 deg
extrude "(All) Pickup Holes" cut sketch "(ALL) Pocket Layout" distance "d225" = 12.7; taper "d226" = 0 deg
node "0.220 plane"
node "1.000 Plane"
node "1.605 Plane"
extrude "(All) Ferral Holes" cut sketch "(ALL) Pocket Layout" stored distance "d208" = 16.637; taper "d209" = 0 deg
sketch "Instructions"
  geometry: L1 (-206.863, 176.532)-(142.802, 176.532); L2 (142.802, 176.532)-(142.802, 128.927); L3 (142.802, 128.927)-(-206.863, 128.927); L4 (-206.863, 128.927)-(-206.863, 176.532); L5 (-55.693, -76.531)-(-54.491, 0) reference; L6 (-54.491, 0)-(0, 0) reference; L7 (0, 0)-(1.202, -76.531) reference; L8 (-1.972, -79.756)-(-20.387, -79.756) reference; L9 (-20.895, -80.264)-(-20.895, -87.503) reference; L10 (-20.387, -88.011)-(-34.103, -88.011) reference; L11 (-33.595, -87.503)-(-33.595, -80.264) reference; L12 (-34.103, -79.756)-(-52.518, -79.756) reference; L13 (-205.045, 80.01)-(-205.045, -485.14) reference; L14 (-205.045, -485.14)-(150.555, -485.14) reference; L15 (150.555, -485.14)-(150.555, 80.01) reference; L16 (-205.045, 80.01)-(150.555, 80.01) reference; A1 r 3.175 centre (-52.518, -76.581) between (-55.693, -76.531) and (-52.518, -79.756) reference; A2 r 3.175 centre (-1.972, -76.581) between (-1.972, -79.756) and (1.202, -76.531) reference; A3 r 0.508 centre (-20.387, -80.264) between (-20.387, -79.756) and (-20.895, -80.264) reference; A4 r 0.508 centre (-20.387, -87.503) between (-20.895, -87.503) and (-20.387, -88.011) reference; A5 r 0.508 centre (-34.103, -87.503) between (-34.103, -88.011) and (-33.595, -87.503) reference; A6 r 0.508 centre (-34.103, -80.264) between (-33.595, -80.264) and (-34.103, -79.756) reference
  constraints: 2 other
extrude "DC Body" sketch "DC Profile" distance "d164" = 44.45; taper "d165" = 0 deg
extrude "DC Electronics Pocket" cut sketch "DC Profile" stored distance "d311" = 0; taper "d312" = 0 deg
extrude "DC Elect. Pocket lip" cut sketch "DC Profile" stored distance "d313" = 0; taper "d314" = 0 deg
extrude "DC Elect. Holes" cut sketch "DC Profile" distance "d371" = 9.525; taper "d372" = 0 deg
fillet "DC 0.020 Fillet" dims "d210" = 0.508
fillet "DC 0.250 Fillet" dims "d211" = 6.35
extrude "SC Body" sketch "SC Profile" distance "d170" = 44.45; taper "d171" = 0 deg
extrude "SC Electronics Pocket" cut sketch "SC Profile" stored distance "d327" = 0; taper "d328" = 0 deg
extrude "SC Elect. Pocket Lip" cut sketch "SC Profile" stored distance "d329" = 0; taper "d330" = 0 deg
extrude "SC Elect.Holes" cut sketch "SC Profile" distance "d381" = 9.525; taper "d382" = 0 deg
fillet "SC 0.020 Fillet" dims "d213" = 0.508
fillet "SC 0.250 Fillet" dims "d212" = 6.35
extrude "Surf Body" sketch "Surf Profile" distance "d172" = 44.45; taper "d173" = 0 deg
extrude "Surf Electronics Pocket" cut sketch "Surf Profile" stored distance "d348" = 0; taper "d349" = 0 deg
extrude "Surt Elect. Pocket Lip" cut sketch "Surf Profile" stored distance "d350" = 44.45; taper "d351" = 0 deg
extrude "Surf Elect. Holes" cut sketch "Surf Profile" distance "d383" = 9.525; taper "d384" = 0 deg
fillet "Surf 0.020 Fillet" dims "d214" = 0.508
fillet "Surf 0.250 Fillet" dims "d215" = 6.35
extrude "Wave Body" sketch "Wave Profile" distance "d303" = 44.45; taper "d304" = 0 deg
extrude "Wave Electronics Pocket" cut sketch "Wave Profile" stored distance "d364" = 25.4; taper "d365" = 0 deg
extrude "Wave Elect. Pocket Lip" cut sketch "Wave Profile" stored distance "d366" = 0; taper "d367" = 0 deg
extrude "Wave Elect. Holes" cut sketch "Wave Profile" distance "d385" = 9.525; taper "d386" = 0 deg
fillet "Wave 0.020 Fillet" dims "d306" = 0.508
fillet "Wave 0.250 Fillet" dims "d305" = 6.35
extrude "Flame Body" sketch "Flame Profile" distance "d174" = 44.45; taper "d175" = 0 deg
extrude "Flame Electronics Pocket" cut sketch "Flame Profile" stored distance "d507" = 25.4; taper "d508" = 0 deg
extrude "Flame Elect. Pocket Lip" cut sketch "Flame Profile" stored distance "d453" = 9.525; taper "d454" = 0 deg
extrude "Flame Elect. Holes" cut sketch "Flame Profile" distance "d449" = 9.525; taper "d450" = 0 deg
fillet "Flame 0.050 Fillet" dims "d216" = 1.27
fillet "Flame 0.250 Fillet" dims "d217" = 6.35
extrude "Axe Body" sketch "Axe Profile" distance "d245" = 44.45; taper "d246" = 0 deg
extrude "Axe Electronics Pocket" cut sketch "Axe Profile" stored distance "d457" = 9.525; taper "d458" = 0 deg
extrude "Axe Elect. Pocket Lip" cut sketch "Axe Profile" stored distance "d459" = 9.525; taper "d460" = 0 deg
extrude "Axe Elect. Holes" cut sketch "Axe Profile" distance "d461" = 9.525; taper "d462" = 0 deg
fillet "Axe 0.075 Fillet" dims "d247" = 1.905
fillet "Axe 0.250 Fillet" dims "d248" = 6.35
extrude "Tear drop Body" sketch "Tear drop Profile" distance "d270" = 44.45; taper "d271" = 0 deg
extrude "Tear Drop Electronics Pocket" cut sketch "Tear drop Profile" stored distance "d495" = 9.525; taper "d496" = 0 deg
extrude "Tear Drop Elect. Path" cut sketch "Tear drop Profile" stored distance "d498" = 9.525; taper "d499" = 0 deg
extrude "Tear Drop Elect. Lip" cut sketch "Tear drop Profile" stored distance "d500" = 9.525; taper "d501" = 0 deg
extrude "Tear Drop Elect. Holes" cut sketch "Tear drop Profile" distance "d505" = 9.525; taper "d506" = 0 deg
fillet "Tear Drop 0.050 Fillet" dims "d272" = 1.27
fillet "Tear Drop 0.250 Fillet" dims "d273" = 6.35
workplane "Work Plane7"
sketch "Sketch35"
  geometry: L1 (8.442, -239.522)-(8.442, -227.33) reference; L2 (8.95, -226.822)-(15.935, -226.822) reference; L3 (15.935, -226.822)-(15.935, -210.312) reference; L4 (15.935, -210.312)-(8.95, -210.312) reference; L5 (8.442, -209.804)-(8.442, -197.612) reference; L6 (8.442, -197.612)-(-62.932, -197.612) reference; L7 (-62.932, -197.612)-(-62.932, -209.804) reference; L8 (-63.44, -210.312)-(-70.425, -210.312) reference; L9 (-70.425, -210.312)-(-70.425, -226.822) reference; L10 (-70.425, -226.822)-(-63.44, -226.822) reference; L11 (-62.932, -227.33)-(-62.932, -239.522) reference; L12 (-62.932, -239.522)-(8.442, -239.522) reference; L13 (8.442, -239.522)-(133.706, -376.99); C1 r 4.762 at (63.065, -329.775) reference; C2 r 6.223 at (53.07, -286.463) reference; A1 r 0.508 centre (8.95, -227.33) between (8.95, -226.822) and (8.442, -227.33) reference; A2 r 0.508 centre (8.95, -209.804) between (8.442, -209.804) and (8.95, -210.312) reference; A3 r 0.508 centre (-63.44, -209.804) between (-63.44, -210.312) and (-62.932, -209.804) reference; A4 r 0.508 centre (-63.44, -227.33) between (-62.932, -227.33) and (-63.44, -226.822) reference; A5 r 121.641 centre (-34.061, -308.562) between (66.507, -376.99) and (83.846, -278.658) reference; A6 r 31.75 centre (53.07, -286.463) between (83.846, -278.658) and (22.023, -279.82) reference; A7 r 1049.401 centre (1048.196, -499.393) between (22.023, -279.82) and (8.81, -354.753) reference; A8 r 31.75 centre (40.257, -359.129) between (8.81, -354.753) and (66.507, -376.99) reference; A9 r 38.1 centre (40.257, -359.129) between (2.521, -353.878) and (71.757, -380.562) reference; A10 r 1055.751 centre (1048.196, -499.393) between (15.814, -278.491) and (2.521, -353.878) reference; A11 r 38.1 centre (53.07, -286.463) between (90.001, -277.097) and (15.814, -278.491) reference; A12 r 127.991 centre (-34.061, -308.562) between (71.757, -380.562) and (90.001, -277.097) reference; A13 r 85.725 centre (49.609, -332.128) between (59.079, -417.328) and (118.036, -280.49) reference; 1 further point
  constraints: 2 end point
  node "Projected Loop167"
  node "Projected Loop168"
workplane "Work Plane8"
sketch "Sketch36"
  geometry: 3 further points
  constraints: 1 coincident
hole "surf drill" sketch "Sketch36" at (0, 0) diameter "d530" = 7.9375; stored, may be unused: countersink angle "d534" = 82 deg, drill point angle "d536" = 0 deg; dims "d531" = 19.05, "d532" = 22.225, "d533" = 50.8, "d535" = 203.2
sketch "Sketch37"
  geometry: L1 (28.829, -25.4)-(28.829, -8.763) reference; L2 (56.681, -8.763)-(13.141, -8.763) reference; L3 (42.037, -25.4)-(42.037, -8.763) reference; 2 further points
hole "Hole2" sketch "Sketch37" at (34.911, -17.081) diameter "d537" = 7.9375; stored, may be unused: countersink angle "d541" = 82 deg, drill point angle "d543" = 0 deg; dims "d538" = 19.05, "d539" = 22.225, "d540" = 50.8, "d542" = 76.2
body "Solid1"
body "Solid2"
other parameters: "d6" = 41.91, "d23" = 8.255, "d207" = -39.37, "d266" = 609.6, "d310" = -40.767, "d497" = -25.4, "d529" = -22.225
